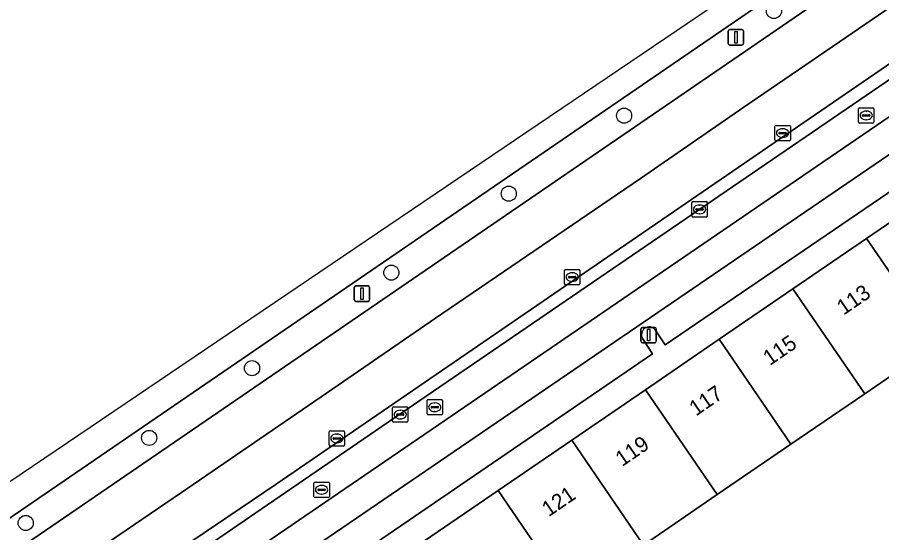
# Model space of a CAD drawing. Extents: x 158086 to 159499, y 382904 to 383981.
# Drawn here: x 158153 to 158208.9, y 383332.3 to 383365.7 of the extents above; entities that cross this region are included whole.
import ezdxf

# ---------------------------------------------------------------- set-up
doc = ezdxf.new("R2010")
doc.units = 0
for name, color, linetype in [('IMGEO_Berm_groen', 7, 'Continuous'), ('IMGEO_Boom', 7, 'Continuous'), ('IMGEO_Erf', 7, 'Continuous'), ('IMGEO_Fietspad_gesloten', 7, 'Continuous'), ('IMGEO_Groenvoorziening', 7, 'Continuous'), ('IMGEO_Haag', 7, 'Continuous'), ('IMGEO_Kolk', 7, 'Continuous'), ('IMGEO_Lichtmast', 7, 'Continuous'), ('IMGEO_OVBaan_gesloten', 7, 'Continuous'), ('IMGEO_Pand', 7, 'Continuous'), ('IMGEO_Pand_nummerreeks', 7, 'Continuous'), ('IMGEO_Parkeervlak_open', 7, 'Continuous'), ('IMGEO_Rijbaan_lokaal_open', 7, 'Continuous'), ('IMGEO_Rijbaan_regionaal_gesloten', 7, 'Continuous'), ('IMGEO_Rioolput', 7, 'Continuous'), ('IMGEO_Voetpad_open', 7, 'Continuous')]:
    doc.layers.add(name, color=color, linetype=linetype)

msp = doc.modelspace()

# ---------------------------------------------------------------- linework, layer by layer
at = {"layer": 'IMGEO_Berm_groen'}
msp.add_lwpolyline([(158226.339, 383381.483), (158291.923, 383426.355), (158293.27, 383427.277), (158296.765, 383429.673), (158295.539, 383431.28), (158292.413, 383429.156), (158290.775, 383428.034), (158225.683, 383383.423), (158126.488, 383315.5), (158126.593, 383315.309), (158120.71, 383311.282), (158122.274, 383309.273), (158125.748, 383312.11), (158126.526, 383312.744), (158131.316, 383316.373), (158152.807, 383331.103)], close=True, dxfattribs=at)
at = {"layer": 'IMGEO_Boom'}
for centre in [(158201.955, 383366.098), (158192.253, 383359.324), (158184.786, 383354.275), (158177.188, 383349.163), (158168.17, 383342.978), (158161.506, 383338.464), (158153.518, 383332.961)]:
    msp.add_circle(centre, 0.489, dxfattribs=at)
at = {"layer": 'IMGEO_Erf'}
msp.add_lwpolyline([(158212.597, 383344.59), (158207.828, 383341.326), (158203.058, 383338.062), (158198.288, 383334.797), (158193.518, 383331.533)], dxfattribs=at)
at = {"layer": 'IMGEO_Fietspad_gesloten'}
for points in [[(158297.888, 383419.791), (158249.821, 383386.895), (158168.177, 383331.08), (158135.484, 383308.657), (158134.382, 383307.926)], [(158135.397, 383306.178), (158136.974, 383307.252), (158143.087, 383311.47), (158147.419, 383314.412), (158148.903, 383315.422), (158169.017, 383329.233), (158213.468, 383359.564), (158215.037, 383360.634), (158222.335, 383365.611), (158224.11, 383366.822), (158241.211, 383378.556), (158242.15, 383379.174), (158250.459, 383384.895), (158251.136, 383385.346), (158251.53, 383385.606), (158287.104, 383409.987)]]:
    msp.add_lwpolyline(points, dxfattribs=at)
at = {"layer": 'IMGEO_Groenvoorziening'}
msp.add_lwpolyline([(158296.668, 383422.637), (158250.34, 383390.703), (158239.558, 383383.344), (158169.725, 383335.466), (158142.338, 383316.977), (158135.713, 383312.45), (158136.281, 383311.619), (158143.906, 383316.851), (158156.489, 383325.454), (158158.334, 383326.705), (158177.739, 383340.005), (158216.514, 383366.493)], dxfattribs=at)
at = {"layer": 'IMGEO_Haag'}
msp.add_lwpolyline([(158296.668, 383422.637), (158250.34, 383390.703), (158239.558, 383383.344), (158169.725, 383335.466), (158142.338, 383316.977), (158135.713, 383312.45), (158136.281, 383311.619), (158143.906, 383316.851), (158156.489, 383325.454), (158158.334, 383326.705), (158177.739, 383340.005), (158216.514, 383366.493)], dxfattribs=at)
at = {"layer": 'IMGEO_Kolk'}
for p, q in [((158202.015, 383357.77), (158202.015, 383358.622)), ((158202.09, 383358.696), (158202.942, 383358.696)), ((158202.503, 383358.476), (158202.528, 383358.476)), ((158203.016, 383358.622), (158203.016, 383357.77)), ((158202.274, 383358.19), (158202.274, 383358.202)), ((158202.712, 383358.153), (158202.314, 383358.153)), ((158202.317, 383358.239), (158202.715, 383358.239)), ((158202.526, 383357.916), (158202.501, 383357.916)), ((158202.758, 383358.202), (158202.758, 383358.19)), ((158202.942, 383357.696), (158202.09, 383357.696)), ((158196.641, 383352.833), (158196.641, 383353.685)), ((158196.716, 383353.759), (158197.568, 383353.759)), ((158197.129, 383353.539), (158197.154, 383353.539)), ((158197.642, 383353.685), (158197.642, 383352.833)), ((158196.9, 383353.253), (158196.9, 383353.265)), ((158197.338, 383353.216), (158196.94, 383353.216)), ((158196.943, 383353.302), (158197.341, 383353.302)), ((158197.152, 383352.979), (158197.127, 383352.979)), ((158197.384, 383353.265), (158197.384, 383353.253)), ((158197.568, 383352.759), (158196.716, 383352.759)), ((158188.396, 383348.449), (158188.396, 383349.301)), ((158188.471, 383349.375), (158189.323, 383349.375)), ((158188.655, 383348.869), (158188.655, 383348.881)), ((158188.698, 383348.918), (158189.096, 383348.918)), ((158188.884, 383349.155), (158188.909, 383349.155)), ((158189.139, 383348.881), (158189.139, 383348.869)), ((158189.397, 383349.301), (158189.397, 383348.449)), ((158189.323, 383348.375), (158188.471, 383348.375)), ((158189.093, 383348.832), (158188.695, 383348.832)), ((158188.907, 383348.595), (158188.882, 383348.595)), ((158177.262, 383339.552), (158177.262, 383340.404)), ((158177.337, 383340.478), (158178.189, 383340.478)), ((158177.521, 383339.972), (158177.521, 383339.984)), ((158177.959, 383339.935), (158177.561, 383339.935)), ((158177.564, 383340.021), (158177.962, 383340.021)), ((158177.75, 383340.258), (158177.775, 383340.258)), ((158178.005, 383339.984), (158178.005, 383339.972)), ((158178.263, 383340.404), (158178.263, 383339.552)), ((158178.189, 383339.478), (158177.337, 383339.478)), ((158177.773, 383339.698), (158177.748, 383339.698)), ((158173.163, 383338.007), (158173.163, 383338.859)), ((158173.238, 383338.933), (158174.09, 383338.933)), ((158174.164, 383338.859), (158174.164, 383338.007)), ((158173.422, 383338.427), (158173.422, 383338.439)), ((158173.86, 383338.39), (158173.462, 383338.39)), ((158173.465, 383338.476), (158173.863, 383338.476)), ((158173.651, 383338.713), (158173.676, 383338.713)), ((158173.906, 383338.439), (158173.906, 383338.427)), ((158174.09, 383337.933), (158173.238, 383337.933)), ((158173.674, 383338.153), (158173.649, 383338.153))]:
    msp.add_line(p, q, dxfattribs=at)
for points in [[(158202.015, 383357.77), (158202.015, 383358.622)], [(158202.09, 383358.696), (158202.942, 383358.696)], [(158203.016, 383358.622), (158203.016, 383357.77)], [(158202.942, 383357.696), (158202.09, 383357.696)], [(158196.641, 383352.833), (158196.641, 383353.685)], [(158196.716, 383353.759), (158197.568, 383353.759)], [(158197.642, 383353.685), (158197.642, 383352.833)], [(158197.568, 383352.759), (158196.716, 383352.759)], [(158188.396, 383348.449), (158188.396, 383349.301)], [(158188.471, 383349.375), (158189.323, 383349.375)], [(158189.397, 383349.301), (158189.397, 383348.449)], [(158189.323, 383348.375), (158188.471, 383348.375)], [(158177.262, 383339.552), (158177.262, 383340.404)], [(158177.337, 383340.478), (158178.189, 383340.478)], [(158178.263, 383340.404), (158178.263, 383339.552)], [(158178.189, 383339.478), (158177.337, 383339.478)], [(158173.163, 383338.007), (158173.163, 383338.859)], [(158173.238, 383338.933), (158174.09, 383338.933)], [(158174.164, 383338.859), (158174.164, 383338.007)], [(158174.09, 383337.933), (158173.238, 383337.933)]]:
    msp.add_lwpolyline(points, dxfattribs=at)
for centre, radius, start, end in [((158202.092, 383358.62), 0.0765, 91.552, 178.448), ((158202.092, 383358.62), 0.0765, 91.552, 178.448), ((158202.94, 383358.62), 0.0765, 1.552, 88.448), ((158202.94, 383358.62), 0.0765, 1.552, 88.448), ((158202.314, 383358.199), 0.0403, 85.8775, 175.7526), ((158202.311, 383358.189), 0.0366, 178.938, 274.7102), ((158202.715, 383358.196), 0.043, 264.8664, 352.4533), ((158202.719, 383358.201), 0.0386, 1.7309, 96.639), ((158202.092, 383357.772), 0.0765, 181.552, 268.448), ((158202.092, 383357.772), 0.0765, 181.552, 268.448), ((158202.94, 383357.772), 0.0765, 271.552, 358.448), ((158202.94, 383357.772), 0.0765, 271.552, 358.448), ((158196.718, 383353.683), 0.0765, 91.552, 178.448), ((158196.718, 383353.683), 0.0765, 91.552, 178.448), ((158197.566, 383353.683), 0.0765, 1.552, 88.448), ((158197.566, 383353.683), 0.0765, 1.552, 88.448), ((158196.718, 383352.835), 0.0765, 181.552, 268.448), ((158196.718, 383352.835), 0.0765, 181.552, 268.448), ((158196.94, 383353.262), 0.0403, 85.8775, 175.7526), ((158196.937, 383353.252), 0.0366, 178.938, 274.7102), ((158197.341, 383353.259), 0.043, 264.8664, 352.4533), ((158197.345, 383353.264), 0.0386, 1.7309, 96.639), ((158197.566, 383352.835), 0.0765, 271.552, 358.448), ((158197.566, 383352.835), 0.0765, 271.552, 358.448), ((158188.473, 383349.299), 0.0765, 91.552, 178.448), ((158188.473, 383349.299), 0.0765, 91.552, 178.448), ((158188.695, 383348.878), 0.0403, 85.8775, 175.7526), ((158189.1, 383348.88), 0.0386, 1.7309, 96.639), ((158189.321, 383349.299), 0.0765, 1.552, 88.448), ((158189.321, 383349.299), 0.0765, 1.552, 88.448), ((158188.473, 383348.451), 0.0765, 181.552, 268.448), ((158188.473, 383348.451), 0.0765, 181.552, 268.448), ((158188.692, 383348.868), 0.0366, 178.938, 274.7102), ((158189.096, 383348.875), 0.043, 264.8664, 352.4533), ((158189.321, 383348.451), 0.0765, 271.552, 358.448), ((158189.321, 383348.451), 0.0765, 271.552, 358.448), ((158177.339, 383340.402), 0.0765, 91.552, 178.448), ((158177.339, 383340.402), 0.0765, 91.552, 178.448), ((158177.561, 383339.981), 0.0403, 85.8775, 175.7526), ((158177.558, 383339.971), 0.0366, 178.938, 274.7102), ((158177.962, 383339.978), 0.043, 264.8664, 352.4533), ((158177.966, 383339.983), 0.0386, 1.7309, 96.639), ((158178.187, 383340.402), 0.0765, 1.552, 88.448), ((158178.187, 383340.402), 0.0765, 1.552, 88.448), ((158177.339, 383339.554), 0.0765, 181.552, 268.448), ((158177.339, 383339.554), 0.0765, 181.552, 268.448), ((158178.187, 383339.554), 0.0765, 271.552, 358.448), ((158178.187, 383339.554), 0.0765, 271.552, 358.448), ((158173.24, 383338.857), 0.0765, 91.552, 178.448), ((158173.24, 383338.857), 0.0765, 91.552, 178.448), ((158174.088, 383338.857), 0.0765, 1.552, 88.448), ((158174.088, 383338.857), 0.0765, 1.552, 88.448), ((158173.462, 383338.436), 0.0403, 85.8775, 175.7526), ((158173.459, 383338.426), 0.0366, 178.938, 274.7102), ((158173.863, 383338.433), 0.043, 264.8664, 352.4533), ((158173.867, 383338.438), 0.0386, 1.7309, 96.639), ((158173.24, 383338.009), 0.0765, 181.552, 268.448), ((158173.24, 383338.009), 0.0765, 181.552, 268.448), ((158174.088, 383338.009), 0.0765, 271.552, 358.448), ((158174.088, 383338.009), 0.0765, 271.552, 358.448)]:
    msp.add_arc(centre, radius, start, end, dxfattribs=at)
for centre, major_axis, ratio, start_param, end_param in [((158202.502, 383358.196), (-0.387, 0.002), 0.722429, 4.712389, 7.853982), ((158202.527, 383358.196), (-0.39, 0.002), 0.717154, 1.570796, 4.712389), ((158197.128, 383353.259), (-0.387, 0.002), 0.722429, 4.712389, 7.853982), ((158197.153, 383353.259), (-0.39, 0.002), 0.717154, 1.570796, 4.712389), ((158188.883, 383348.875), (-0.387, 0.002), 0.722429, 4.712389, 7.853982), ((158188.908, 383348.875), (-0.39, 0.002), 0.717154, 1.570796, 4.712389), ((158177.749, 383339.978), (-0.387, 0.002), 0.722429, 4.712389, 7.853982), ((158177.774, 383339.978), (-0.39, 0.002), 0.717154, 1.570796, 4.712389), ((158173.65, 383338.433), (-0.387, 0.002), 0.722429, 4.712389, 7.853982), ((158173.675, 383338.433), (-0.39, 0.002), 0.717154, 1.570796, 4.712389)]:
    msp.add_ellipse(centre, major_axis=major_axis, ratio=ratio, start_param=start_param, end_param=end_param, dxfattribs=at)
at = {"layer": 'IMGEO_Lichtmast'}
for p, q in [((158198.994, 383363.998), (158198.994, 383364.798)), ((158198.994, 383364.798), (158198.994, 383363.998)), ((158199.094, 383364.898), (158199.884, 383364.898)), ((158199.884, 383364.898), (158199.094, 383364.898)), ((158199.984, 383364.798), (158199.984, 383363.998)), ((158199.984, 383363.998), (158199.984, 383364.798)), ((158199.884, 383363.898), (158199.094, 383363.898)), ((158199.094, 383363.898), (158199.884, 383363.898)), ((158174.789, 383347.4), (158174.789, 383348.2)), ((158174.789, 383348.2), (158174.789, 383347.4)), ((158174.889, 383348.3), (158175.679, 383348.3)), ((158175.679, 383348.3), (158174.889, 383348.3)), ((158175.779, 383348.2), (158175.779, 383347.4)), ((158175.779, 383347.4), (158175.779, 383348.2)), ((158175.679, 383347.3), (158174.889, 383347.3)), ((158174.889, 383347.3), (158175.679, 383347.3)), ((158193.345, 383344.721), (158193.345, 383345.521)), ((158193.345, 383345.521), (158193.345, 383344.721)), ((158193.445, 383345.621), (158194.235, 383345.621)), ((158194.235, 383345.621), (158193.445, 383345.621)), ((158194.335, 383345.521), (158194.335, 383344.721)), ((158194.335, 383344.721), (158194.335, 383345.521)), ((158194.235, 383344.621), (158193.445, 383344.621)), ((158193.445, 383344.621), (158194.235, 383344.621))]:
    msp.add_line(p, q, dxfattribs=at)
for points in [[(158199.414, 383364.773), (158199.564, 383364.773), (158199.564, 383364.023), (158199.414, 383364.023), (158199.414, 383364.773)], [(158175.209, 383348.175), (158175.359, 383348.175), (158175.359, 383347.425), (158175.209, 383347.425), (158175.209, 383348.175)], [(158193.765, 383345.496), (158193.915, 383345.496), (158193.915, 383344.746), (158193.765, 383344.746), (158193.765, 383345.496)]]:
    msp.add_lwpolyline(points, dxfattribs=at)
for centre, start, end in [((158199.094, 383364.798), 90, 180), ((158199.094, 383364.798), 90, 180), ((158199.884, 383364.798), 0, 90), ((158199.884, 383364.798), 360, 90), ((158199.094, 383363.998), 180, 270), ((158199.094, 383363.998), 180, 270), ((158199.884, 383363.998), 270, 0), ((158199.884, 383363.998), 270, 0), ((158174.889, 383348.2), 90, 180), ((158174.889, 383348.2), 90, 180), ((158175.679, 383348.2), 0, 90), ((158175.679, 383348.2), 360, 90), ((158174.889, 383347.4), 180, 270), ((158174.889, 383347.4), 180, 270), ((158175.679, 383347.4), 270, 0), ((158175.679, 383347.4), 270, 0), ((158193.445, 383345.521), 90, 180), ((158193.445, 383345.521), 90, 180), ((158194.235, 383345.521), 0, 90), ((158194.235, 383345.521), 360, 90), ((158193.445, 383344.721), 180, 270), ((158193.445, 383344.721), 180, 270), ((158194.235, 383344.721), 270, 0), ((158194.235, 383344.721), 270, 0)]:
    msp.add_arc(centre, 0.1, start, end, dxfattribs=at)
at = {"layer": 'IMGEO_OVBaan_gesloten'}
msp.add_lwpolyline([(158290.829, 383429.195), (158142.057, 383328.583), (158135.353, 383324.049), (158105.383, 383303.781), (158106.799, 383301.782), (158111.95, 383305.28), (158120.71, 383311.282), (158126.593, 383315.309), (158126.488, 383315.5), (158225.683, 383383.423), (158290.775, 383428.034)], dxfattribs=at)
at = {"layer": 'IMGEO_Pand'}
for points in [[(158212.597, 383344.59), (158217.367, 383347.854), (158212.725, 383354.634), (158207.953, 383351.372)], [(158212.597, 383344.59), (158207.953, 383351.372), (158203.182, 383348.11), (158207.828, 383341.326)], [(158207.828, 383341.326), (158203.182, 383348.11), (158198.411, 383344.848), (158203.058, 383338.062)], [(158198.288, 383334.797), (158203.058, 383338.062), (158198.411, 383344.848), (158193.64, 383341.586)], [(158198.288, 383334.797), (158193.64, 383341.586), (158188.869, 383338.324), (158193.518, 383331.533)], [(158184.097, 383335.061), (158188.748, 383328.269), (158193.518, 383331.533), (158188.869, 383338.324)], [(158184.097, 383335.061), (158179.326, 383331.799), (158183.978, 383325.005), (158188.748, 383328.269)]]:
    msp.add_lwpolyline(points, close=True, dxfattribs=at)
at = {"layer": 'IMGEO_Parkeervlak_open'}
for points in [[(158213.468, 383359.564), (158169.017, 383329.233), (158148.903, 383315.422)], [(158194.267, 383345.466), (158194.911, 383344.488), (158213.785, 383357.36), (158213.222, 383358.174)], [(158169.94, 383328.812), (158170.579, 383327.839), (158194.098, 383343.91), (158193.456, 383344.892)]]:
    msp.add_lwpolyline(points, dxfattribs=at)
msp.add_arc((158193.88, 383345.153), 0.498, 38.9695, 211.6098, dxfattribs=at)
at = {"layer": 'IMGEO_Rijbaan_lokaal_open'}
for points in [[(158135.494, 383309.526), (158135.588, 383309.03), (158135.484, 383308.657), (158168.177, 383331.08), (158249.821, 383386.895), (158297.888, 383419.791), (158299.772, 383421.047), (158299.394, 383421.023), (158298.978, 383421.305)], [(158296.713, 383421.366), (158288.26, 383415.605), (158270.547, 383403.457), (158248.501, 383388.378), (158235.922, 383379.756), (158216.514, 383366.493), (158177.739, 383340.005), (158158.334, 383326.705), (158156.489, 383325.454), (158143.906, 383316.851), (158136.281, 383311.619)]]:
    msp.add_lwpolyline(points, dxfattribs=at)
at = {"layer": 'IMGEO_Rijbaan_regionaal_gesloten'}
for points in [[(158291.923, 383426.355), (158226.339, 383381.483), (158152.807, 383331.103), (158131.316, 383316.373), (158126.526, 383312.744), (158125.748, 383312.11), (158122.274, 383309.273), (158117.034, 383305.405), (158108.377, 383299.51), (158110.059, 383297.015), (158120.725, 383304.43), (158130.088, 383311.713), (158140.153, 383318.963), (158150.139, 383325.717), (158153.45, 383328.028), (158163.611, 383334.93), (158173.4, 383341.65), (158180.047, 383346.206), (158193.317, 383355.261), (158200.003, 383359.875), (158206.611, 383364.391), (158296.442, 383425.805)], [(158296.442, 383425.805), (158206.611, 383364.391), (158200.003, 383359.875), (158193.317, 383355.261), (158180.047, 383346.206), (158173.4, 383341.65), (158163.611, 383334.93), (158153.45, 383328.028), (158150.139, 383325.717), (158140.153, 383318.963), (158130.088, 383311.713), (158120.725, 383304.43), (158110.059, 383297.015), (158111.752, 383294.502), (158116.714, 383297.886), (158119.385, 383299.725), (158121.038, 383300.856), (158122.649, 383302.057), (158124.994, 383303.909), (158127.323, 383305.803), (158128.269, 383306.604)], [(158135.533, 383312.327), (158135.713, 383312.45), (158142.338, 383316.977), (158169.725, 383335.466), (158239.558, 383383.344), (158250.34, 383390.703), (158296.668, 383422.637)]]:
    msp.add_lwpolyline(points, dxfattribs=at)
at = {"layer": 'IMGEO_Rioolput'}
for p, q in [((158207.428, 383358.914), (158207.428, 383359.766)), ((158207.503, 383359.84), (158208.355, 383359.84)), ((158207.916, 383359.62), (158207.941, 383359.62)), ((158208.429, 383359.766), (158208.429, 383358.914)), ((158207.687, 383359.334), (158207.687, 383359.346)), ((158208.125, 383359.297), (158207.727, 383359.297)), ((158207.73, 383359.383), (158208.128, 383359.383)), ((158207.939, 383359.06), (158207.914, 383359.06)), ((158208.171, 383359.346), (158208.171, 383359.334)), ((158208.355, 383358.84), (158207.503, 383358.84)), ((158179.498, 383340.028), (158179.498, 383340.88)), ((158179.573, 383340.954), (158180.425, 383340.954)), ((158179.8, 383340.497), (158180.198, 383340.497)), ((158179.986, 383340.734), (158180.011, 383340.734)), ((158180.499, 383340.88), (158180.499, 383340.028)), ((158180.425, 383339.954), (158179.573, 383339.954)), ((158179.757, 383340.448), (158179.757, 383340.46)), ((158180.195, 383340.411), (158179.797, 383340.411)), ((158180.009, 383340.174), (158179.984, 383340.174)), ((158180.241, 383340.46), (158180.241, 383340.448)), ((158172.174, 383334.682), (158172.174, 383335.534)), ((158172.249, 383335.608), (158173.101, 383335.608)), ((158173.175, 383335.534), (158173.175, 383334.682)), ((158172.433, 383335.102), (158172.433, 383335.114)), ((158172.871, 383335.065), (158172.473, 383335.065)), ((158172.476, 383335.151), (158172.874, 383335.151)), ((158172.662, 383335.388), (158172.687, 383335.388)), ((158172.917, 383335.114), (158172.917, 383335.102)), ((158173.101, 383334.608), (158172.249, 383334.608)), ((158172.685, 383334.828), (158172.66, 383334.828))]:
    msp.add_line(p, q, dxfattribs=at)
for points in [[(158207.428, 383358.914), (158207.428, 383359.766)], [(158207.503, 383359.84), (158208.355, 383359.84)], [(158208.429, 383359.766), (158208.429, 383358.914)], [(158208.355, 383358.84), (158207.503, 383358.84)], [(158179.498, 383340.028), (158179.498, 383340.88)], [(158179.573, 383340.954), (158180.425, 383340.954)], [(158180.499, 383340.88), (158180.499, 383340.028)], [(158180.425, 383339.954), (158179.573, 383339.954)], [(158172.174, 383334.682), (158172.174, 383335.534)], [(158172.249, 383335.608), (158173.101, 383335.608)], [(158173.175, 383335.534), (158173.175, 383334.682)], [(158173.101, 383334.608), (158172.249, 383334.608)]]:
    msp.add_lwpolyline(points, dxfattribs=at)
for centre, radius, start, end in [((158207.505, 383359.764), 0.0765, 91.552, 178.448), ((158207.505, 383359.764), 0.0765, 91.552, 178.448), ((158208.353, 383359.764), 0.0765, 1.552, 88.448), ((158208.353, 383359.764), 0.0765, 1.552, 88.448), ((158207.727, 383359.343), 0.0403, 85.8775, 175.7526), ((158207.724, 383359.333), 0.0366, 178.938, 274.7102), ((158208.128, 383359.34), 0.043, 264.8664, 352.4533), ((158208.132, 383359.345), 0.0386, 1.7309, 96.639), ((158207.505, 383358.916), 0.0765, 181.552, 268.448), ((158207.505, 383358.916), 0.0765, 181.552, 268.448), ((158208.353, 383358.916), 0.0765, 271.552, 358.448), ((158208.353, 383358.916), 0.0765, 271.552, 358.448), ((158179.575, 383340.878), 0.0765, 91.552, 178.448), ((158179.575, 383340.878), 0.0765, 91.552, 178.448), ((158179.797, 383340.457), 0.0403, 85.8775, 175.7526), ((158180.202, 383340.459), 0.0386, 1.7309, 96.639), ((158180.423, 383340.878), 0.0765, 1.552, 88.448), ((158180.423, 383340.878), 0.0765, 1.552, 88.448), ((158179.575, 383340.03), 0.0765, 181.552, 268.448), ((158179.575, 383340.03), 0.0765, 181.552, 268.448), ((158179.794, 383340.447), 0.0366, 178.938, 274.7102), ((158180.198, 383340.454), 0.043, 264.8664, 352.4533), ((158180.423, 383340.03), 0.0765, 271.552, 358.448), ((158180.423, 383340.03), 0.0765, 271.552, 358.448), ((158172.251, 383335.532), 0.0765, 91.552, 178.448), ((158172.251, 383335.532), 0.0765, 91.552, 178.448), ((158173.099, 383335.532), 0.0765, 1.552, 88.448), ((158173.099, 383335.532), 0.0765, 1.552, 88.448), ((158172.473, 383335.111), 0.0403, 85.8775, 175.7526), ((158172.47, 383335.101), 0.0366, 178.938, 274.7102), ((158172.874, 383335.108), 0.043, 264.8664, 352.4533), ((158172.878, 383335.113), 0.0386, 1.7309, 96.639), ((158172.251, 383334.684), 0.0765, 181.552, 268.448), ((158172.251, 383334.684), 0.0765, 181.552, 268.448), ((158173.099, 383334.684), 0.0765, 271.552, 358.448), ((158173.099, 383334.684), 0.0765, 271.552, 358.448)]:
    msp.add_arc(centre, radius, start, end, dxfattribs=at)
for centre, major_axis, ratio, start_param, end_param in [((158207.915, 383359.34), (-0.387, 0.002), 0.722429, 4.712389, 7.853982), ((158207.94, 383359.34), (-0.39, 0.002), 0.717154, 1.570796, 4.712389), ((158179.985, 383340.454), (-0.387, 0.002), 0.722429, 4.712389, 7.853982), ((158180.01, 383340.454), (-0.39, 0.002), 0.717154, 1.570796, 4.712389), ((158172.661, 383335.108), (-0.387, 0.002), 0.722429, 4.712389, 7.853982), ((158172.686, 383335.108), (-0.39, 0.002), 0.717154, 1.570796, 4.712389)]:
    msp.add_ellipse(centre, major_axis=major_axis, ratio=ratio, start_param=start_param, end_param=end_param, dxfattribs=at)
at = {"layer": 'IMGEO_Voetpad_open'}
for points in [[(158150.25, 383311.92), (158155.491, 383315.503), (158160.257, 383318.762), (158165.024, 383322.021), (158169.792, 383325.281), (158174.559, 383328.54), (158179.326, 383331.799), (158184.097, 383335.061), (158188.869, 383338.324), (158193.64, 383341.586), (158198.411, 383344.848), (158203.182, 383348.11), (158207.953, 383351.372), (158212.725, 383354.634), (158217.541, 383357.927), (158220.677, 383360.064), (158222.111, 383361.041), (158223.951, 383362.295), (158228.836, 383365.646), (158233.612, 383368.922)], [(158213.222, 383358.174), (158213.785, 383357.36), (158194.911, 383344.488), (158194.267, 383345.466)], [(158193.456, 383344.892), (158194.098, 383343.91), (158170.579, 383327.839), (158169.94, 383328.812)]]:
    msp.add_lwpolyline(points, dxfattribs=at)
msp.add_arc((158193.88, 383345.153), 0.498, 38.9695, 211.6098, dxfattribs=at)

# ---------------------------------------------------------------- texts
at = {"layer": 'IMGEO_Pand_nummerreeks'}
for s, p in [('113', (158206.462, 383346.378)), ('115', (158201.684, 383343.111)), ('117', (158196.906, 383339.845)), ('119', (158192.128, 383336.578)), ('121', (158187.369, 383333.325))]:
    msp.add_text(s, height=1, rotation=34.3605, dxfattribs=at).set_placement(p)

doc.saveas('drawing.dxf')
